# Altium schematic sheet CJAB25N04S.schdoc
size 127 x 101 mm
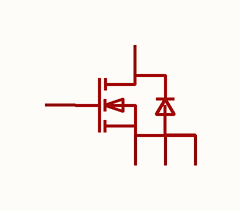
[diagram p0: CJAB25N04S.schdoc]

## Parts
Q?  cjab25n04s  [DFN-8_L3.0-W3.0-P0.65-LS3.1-BL]  (value not drawn)

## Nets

Not connected (* = marked no-connect by the designer): Q? 1(S) 2(S) 3(S) 4(G) 5(D)

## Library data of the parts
Q? = cjab25n04s: 数量:1个N沟道;漏源电压(Vdss):40V;连续漏极电流(Id):25A;导通电阻(RDS(on)):9.4mΩ@10V;耗散功率(Pd):3W;阈值电压(Vgs(th)):1V;; Manufacturer: CJ(江苏长电/长晶); AddInBom: yes; ModelId: 6ce275f581d94be6a0ecbe0ef507fbae; ModelTransform: 129.921,129.921,0,0,0,0,0,0,0; Number: 1个N沟道; Drain to Source Voltage: 40V; Current - Continuous Drain(Id): 25A; Pd - Power Dissipation: 3W; Gate Threshold Voltage (Vgs(th)): 1V; Gate Charge(Qg): 20.3nC@10V; Input Capacitance(Ciss): 1.2nF; Reverse Transfer Capacitance (Crss@Vds): 58pF; Type: N沟道; Output Capacitance(Coss): 124pF; Vgs: ±20V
